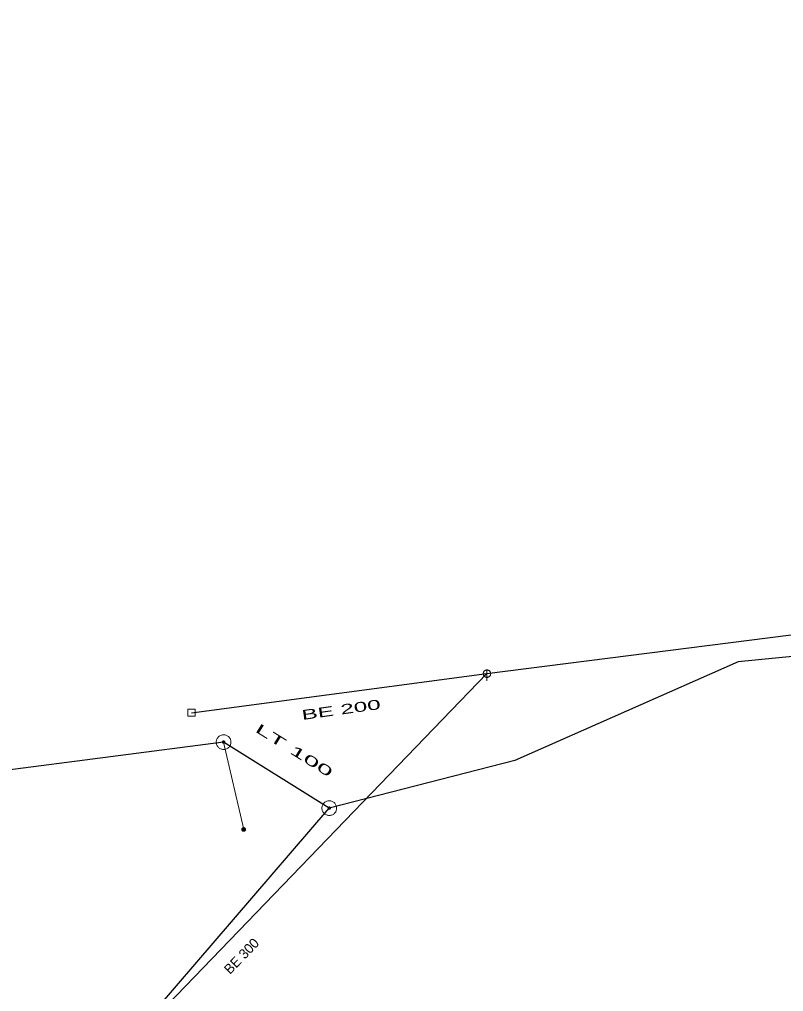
# Model space of a CAD drawing. Extents: x -687515 to -686506, y -974029 to -973461.
# Drawn here: x -687166.1 to -687114.2, y -973704.9 to -973638.9 of the extents above; entities that cross this region are included whole.
import ezdxf
from ezdxf.enums import TextEntityAlignment as Align

# ---------------------------------------------------------------- set-up
doc = ezdxf.new("R2010")
doc.units = 0
doc.header["$LTSCALE"] = 0.27
for name, color, linetype, lineweight in [('1', 7, 'Continuous', 13), ('14', 7, 'Continuous', 25), ('17', 7, 'Continuous', 25), ('22', 7, 'Continuous', 13), ('47', 7, 'Continuous', 13), ('9', 7, 'Continuous', 13)]:
    doc.layers.add(name, color=color, linetype=linetype, lineweight=lineweight)

msp = doc.modelspace()

# ---------------------------------------------------------------- linework, layer by layer
at = {"layer": '14'}
msp.add_line((-687167.553, -973717.772), (-687134.323, -973683.33), dxfattribs=at)
at = {"layer": '14', "lineweight": 13}
msp.add_line((-687152.206, -973687.982), (-687150.845, -973693.919), dxfattribs=at)
at = {"layer": '14'}
msp.add_lwpolyline([(-687154.392, -973685.982), (-687134.323, -973683.33), (-687071.261, -973675.291), (-687084.086, -973638.868)], dxfattribs=at)
at = {"layer": '17'}
for p, q in [((-687152.206, -973687.982), (-687218.589, -973696.579)), ((-687145.032, -973692.468), (-687152.206, -973687.982))]:
    msp.add_line(p, q, dxfattribs=at)
for points in [[(-687070.029, -973676.849), (-687070.692, -973676.951), (-687096.75, -973680.521), (-687117.267, -973682.535), (-687132.432, -973689.241), (-687145.032, -973692.468)], [(-687209.456, -973759.651), (-687158.031, -973707.595), (-687145.032, -973692.468)]]:
    msp.add_lwpolyline(points, dxfattribs=at)
at = {"layer": '22'}
msp.add_line((-687134.322, -973683.078), (-687134.323, -973683.821), dxfattribs=at)
for points in [[(-687134.071, -973683.33), (-687134.072, -973683.304), (-687134.076, -973683.278), (-687134.082, -973683.252), (-687134.092, -973683.228), (-687134.104, -973683.204), (-687134.118, -973683.182), (-687134.135, -973683.161), (-687134.153, -973683.143), (-687134.174, -973683.126), (-687134.196, -973683.112), (-687134.22, -973683.1), (-687134.244, -973683.09), (-687134.27, -973683.084), (-687134.296, -973683.08), (-687134.322, -973683.078), (-687134.348, -973683.079), (-687134.374, -973683.083), (-687134.4, -973683.089), (-687134.425, -973683.099), (-687134.448, -973683.111), (-687134.47, -973683.125), (-687134.491, -973683.142), (-687134.509, -973683.16), (-687134.526, -973683.181), (-687134.54, -973683.203), (-687134.552, -973683.227), (-687134.562, -973683.251), (-687134.569, -973683.277), (-687134.573, -973683.303), (-687134.575, -973683.329), (-687134.574, -973683.355), (-687134.57, -973683.381), (-687134.563, -973683.407), (-687134.553, -973683.432), (-687134.541, -973683.455), (-687134.527, -973683.477), (-687134.51, -973683.498), (-687134.492, -973683.516), (-687134.471, -973683.533), (-687134.449, -973683.547), (-687134.426, -973683.559), (-687134.401, -973683.569), (-687134.375, -973683.576), (-687134.349, -973683.58), (-687134.323, -973683.581), (-687134.297, -973683.581), (-687134.271, -973683.577), (-687134.245, -973683.57), (-687134.221, -973683.56), (-687134.197, -973683.548), (-687134.175, -973683.534), (-687134.154, -973683.517), (-687134.136, -973683.499), (-687134.119, -973683.478), (-687134.105, -973683.456), (-687134.093, -973683.433), (-687134.083, -973683.408), (-687134.077, -973683.382), (-687134.073, -973683.356)], [(-687154.64, -973685.733), (-687154.144, -973685.733), (-687154.144, -973686.23), (-687154.64, -973686.23)]]:
    msp.add_lwpolyline(points, close=True, dxfattribs=at)
at = {"layer": '47'}
for points in [[(-687151.708, -973687.93), (-687151.717, -973687.878), (-687151.73, -973687.828), (-687151.749, -973687.779), (-687151.772, -973687.732), (-687151.801, -973687.688), (-687151.834, -973687.647), (-687151.871, -973687.611), (-687151.912, -973687.578), (-687151.955, -973687.549), (-687152.002, -973687.525), (-687152.051, -973687.506), (-687152.101, -973687.493), (-687152.153, -973687.484), (-687152.205, -973687.482), (-687152.257, -973687.484), (-687152.309, -973687.493), (-687152.359, -973687.506), (-687152.409, -973687.525), (-687152.455, -973687.548), (-687152.499, -973687.577), (-687152.54, -973687.61), (-687152.577, -973687.647), (-687152.61, -973687.688), (-687152.639, -973687.731), (-687152.662, -973687.778), (-687152.681, -973687.827), (-687152.695, -973687.877), (-687152.703, -973687.929), (-687152.705, -973687.981), (-687152.703, -973688.033), (-687152.694, -973688.085), (-687152.681, -973688.135), (-687152.663, -973688.185), (-687152.639, -973688.231), (-687152.61, -973688.275), (-687152.578, -973688.316), (-687152.541, -973688.353), (-687152.5, -973688.386), (-687152.456, -973688.415), (-687152.409, -973688.438), (-687152.36, -973688.457), (-687152.311, -973688.471), (-687152.258, -973688.479), (-687152.206, -973688.481), (-687152.154, -973688.479), (-687152.102, -973688.47), (-687152.052, -973688.457), (-687152.003, -973688.439), (-687151.956, -973688.415), (-687151.912, -973688.386), (-687151.871, -973688.354), (-687151.835, -973688.317), (-687151.802, -973688.276), (-687151.773, -973688.232), (-687151.749, -973688.185), (-687151.73, -973688.136), (-687151.717, -973688.087), (-687151.708, -973688.034), (-687151.706, -973687.982)], [(-687152.124, -973687.973), (-687152.125, -973687.964), (-687152.128, -973687.956), (-687152.13, -973687.949), (-687152.134, -973687.941), (-687152.139, -973687.933), (-687152.145, -973687.927), (-687152.151, -973687.92), (-687152.157, -973687.915), (-687152.165, -973687.911), (-687152.172, -973687.907), (-687152.18, -973687.903), (-687152.189, -973687.901), (-687152.197, -973687.9), (-687152.205, -973687.899), (-687152.214, -973687.9), (-687152.223, -973687.901), (-687152.231, -973687.904), (-687152.238, -973687.906), (-687152.246, -973687.91), (-687152.254, -973687.915), (-687152.26, -973687.921), (-687152.267, -973687.927), (-687152.272, -973687.933), (-687152.277, -973687.941), (-687152.28, -973687.948), (-687152.284, -973687.956), (-687152.286, -973687.965), (-687152.287, -973687.973), (-687152.288, -973687.981), (-687152.287, -973687.99), (-687152.286, -973687.999), (-687152.283, -973688.007), (-687152.281, -973688.014), (-687152.277, -973688.022), (-687152.272, -973688.03), (-687152.267, -973688.036), (-687152.26, -973688.043), (-687152.254, -973688.048), (-687152.246, -973688.053), (-687152.239, -973688.056), (-687152.231, -973688.06), (-687152.222, -973688.062), (-687152.214, -973688.063), (-687152.206, -973688.064), (-687152.197, -973688.063), (-687152.188, -973688.062), (-687152.18, -973688.059), (-687152.173, -973688.057), (-687152.165, -973688.053), (-687152.157, -973688.048), (-687152.151, -973688.043), (-687152.144, -973688.036), (-687152.139, -973688.03), (-687152.135, -973688.022), (-687152.131, -973688.015), (-687152.127, -973688.007), (-687152.125, -973687.998), (-687152.124, -973687.99), (-687152.123, -973687.982)], [(-687144.532, -973692.462), (-687144.535, -973692.41), (-687144.544, -973692.358), (-687144.558, -973692.309), (-687144.577, -973692.26), (-687144.601, -973692.213), (-687144.631, -973692.169), (-687144.664, -973692.13), (-687144.701, -973692.093), (-687144.742, -973692.06), (-687144.786, -973692.032), (-687144.833, -973692.008), (-687144.882, -973691.991), (-687144.933, -973691.977), (-687144.985, -973691.97), (-687145.037, -973691.968), (-687145.089, -973691.971), (-687145.141, -973691.98), (-687145.191, -973691.994), (-687145.239, -973692.013), (-687145.286, -973692.037), (-687145.33, -973692.067), (-687145.37, -973692.1), (-687145.407, -973692.137), (-687145.44, -973692.178), (-687145.467, -973692.222), (-687145.491, -973692.269), (-687145.509, -973692.318), (-687145.522, -973692.369), (-687145.529, -973692.421), (-687145.531, -973692.473), (-687145.528, -973692.525), (-687145.519, -973692.577), (-687145.506, -973692.627), (-687145.486, -973692.675), (-687145.462, -973692.722), (-687145.433, -973692.766), (-687145.4, -973692.806), (-687145.363, -973692.843), (-687145.321, -973692.876), (-687145.277, -973692.903), (-687145.23, -973692.927), (-687145.182, -973692.945), (-687145.13, -973692.958), (-687145.078, -973692.965), (-687145.026, -973692.967), (-687144.974, -973692.964), (-687144.922, -973692.955), (-687144.873, -973692.942), (-687144.824, -973692.922), (-687144.777, -973692.898), (-687144.733, -973692.869), (-687144.694, -973692.836), (-687144.657, -973692.799), (-687144.624, -973692.757), (-687144.596, -973692.713), (-687144.572, -973692.666), (-687144.555, -973692.618), (-687144.541, -973692.566), (-687144.534, -973692.514)], [(-687144.95, -973692.467), (-687144.95, -973692.458), (-687144.952, -973692.45), (-687144.954, -973692.442), (-687144.957, -973692.434), (-687144.961, -973692.426), (-687144.966, -973692.419), (-687144.971, -973692.412), (-687144.977, -973692.406), (-687144.984, -973692.401), (-687144.991, -973692.396), (-687144.999, -973692.392), (-687145.007, -973692.389), (-687145.015, -973692.387), (-687145.023, -973692.385), (-687145.032, -973692.386), (-687145.041, -973692.386), (-687145.049, -973692.388), (-687145.057, -973692.39), (-687145.065, -973692.393), (-687145.073, -973692.397), (-687145.08, -973692.402), (-687145.087, -973692.407), (-687145.093, -973692.413), (-687145.099, -973692.42), (-687145.103, -973692.427), (-687145.107, -973692.435), (-687145.11, -973692.443), (-687145.112, -973692.451), (-687145.114, -973692.459), (-687145.113, -973692.468), (-687145.113, -973692.477), (-687145.111, -973692.485), (-687145.109, -973692.493), (-687145.106, -973692.501), (-687145.102, -973692.509), (-687145.098, -973692.516), (-687145.092, -973692.523), (-687145.086, -973692.529), (-687145.079, -973692.535), (-687145.072, -973692.539), (-687145.064, -973692.543), (-687145.056, -973692.546), (-687145.048, -973692.548), (-687145.04, -973692.55), (-687145.031, -973692.549), (-687145.022, -973692.549), (-687145.014, -973692.547), (-687145.006, -973692.545), (-687144.998, -973692.542), (-687144.99, -973692.538), (-687144.983, -973692.534), (-687144.976, -973692.528), (-687144.97, -973692.522), (-687144.965, -973692.515), (-687144.96, -973692.508), (-687144.956, -973692.5), (-687144.953, -973692.492), (-687144.951, -973692.484), (-687144.949, -973692.476)]]:
    msp.add_lwpolyline(points, close=True, dxfattribs=at)
at = {"layer": '9'}
for points in [[(-687150.718, -973693.919), (-687150.72, -973693.906), (-687150.722, -973693.893), (-687150.725, -973693.88), (-687150.73, -973693.868), (-687150.735, -973693.856), (-687150.743, -973693.845), (-687150.75, -973693.835), (-687150.761, -973693.825), (-687150.771, -973693.817), (-687150.782, -973693.809), (-687150.794, -973693.804), (-687150.806, -973693.799), (-687150.819, -973693.796), (-687150.831, -973693.794), (-687150.845, -973693.793), (-687150.858, -973693.794), (-687150.87, -973693.796), (-687150.884, -973693.799), (-687150.896, -973693.804), (-687150.907, -973693.809), (-687150.919, -973693.817), (-687150.929, -973693.825), (-687150.939, -973693.835), (-687150.946, -973693.845), (-687150.954, -973693.856), (-687150.96, -973693.868), (-687150.965, -973693.88), (-687150.968, -973693.893), (-687150.97, -973693.906), (-687150.971, -973693.919), (-687150.97, -973693.932), (-687150.968, -973693.945), (-687150.965, -973693.958), (-687150.96, -973693.97), (-687150.954, -973693.982), (-687150.946, -973693.993), (-687150.939, -973694.003), (-687150.929, -973694.013), (-687150.919, -973694.021), (-687150.907, -973694.028), (-687150.896, -973694.034), (-687150.884, -973694.039), (-687150.87, -973694.042), (-687150.858, -973694.044), (-687150.845, -973694.045), (-687150.831, -973694.044), (-687150.819, -973694.042), (-687150.806, -973694.039), (-687150.794, -973694.034), (-687150.782, -973694.028), (-687150.771, -973694.021), (-687150.761, -973694.013), (-687150.75, -973694.003), (-687150.743, -973693.993), (-687150.735, -973693.982), (-687150.73, -973693.97), (-687150.725, -973693.958), (-687150.722, -973693.945), (-687150.72, -973693.932)], [(-687150.739, -973693.919), (-687150.739, -973693.907), (-687150.74, -973693.897), (-687150.744, -973693.886), (-687150.748, -973693.876), (-687150.753, -973693.866), (-687150.759, -973693.857), (-687150.766, -973693.848), (-687150.774, -973693.84), (-687150.782, -973693.833), (-687150.792, -973693.827), (-687150.802, -973693.822), (-687150.811, -973693.818), (-687150.823, -973693.815), (-687150.833, -973693.813), (-687150.845, -973693.813), (-687150.856, -973693.813), (-687150.867, -973693.815), (-687150.878, -973693.818), (-687150.887, -973693.822), (-687150.897, -973693.827), (-687150.907, -973693.833), (-687150.916, -973693.84), (-687150.924, -973693.848), (-687150.931, -973693.857), (-687150.936, -973693.866), (-687150.941, -973693.876), (-687150.946, -973693.886), (-687150.949, -973693.897), (-687150.951, -973693.907), (-687150.951, -973693.919), (-687150.951, -973693.93), (-687150.949, -973693.941), (-687150.946, -973693.952), (-687150.941, -973693.962), (-687150.936, -973693.972), (-687150.931, -973693.981), (-687150.924, -973693.99), (-687150.916, -973693.998), (-687150.907, -973694.005), (-687150.897, -973694.011), (-687150.887, -973694.016), (-687150.878, -973694.02), (-687150.867, -973694.023), (-687150.856, -973694.025), (-687150.845, -973694.025), (-687150.833, -973694.025), (-687150.823, -973694.023), (-687150.811, -973694.02), (-687150.802, -973694.016), (-687150.792, -973694.011), (-687150.782, -973694.005), (-687150.774, -973693.998), (-687150.766, -973693.99), (-687150.759, -973693.981), (-687150.753, -973693.972), (-687150.748, -973693.962), (-687150.744, -973693.952), (-687150.74, -973693.941), (-687150.739, -973693.93)], [(-687150.757, -973693.919), (-687150.759, -973693.91), (-687150.76, -973693.901), (-687150.762, -973693.892), (-687150.766, -973693.884), (-687150.77, -973693.876), (-687150.775, -973693.868), (-687150.781, -973693.861), (-687150.787, -973693.855), (-687150.794, -973693.849), (-687150.802, -973693.844), (-687150.809, -973693.84), (-687150.818, -973693.837), (-687150.826, -973693.834), (-687150.836, -973693.833), (-687150.845, -973693.831), (-687150.853, -973693.833), (-687150.863, -973693.834), (-687150.872, -973693.837), (-687150.88, -973693.84), (-687150.887, -973693.844), (-687150.896, -973693.849), (-687150.902, -973693.855), (-687150.909, -973693.861), (-687150.914, -973693.868), (-687150.919, -973693.876), (-687150.924, -973693.884), (-687150.927, -973693.892), (-687150.929, -973693.901), (-687150.931, -973693.91), (-687150.932, -973693.919), (-687150.931, -973693.928), (-687150.929, -973693.937), (-687150.927, -973693.946), (-687150.924, -973693.954), (-687150.919, -973693.962), (-687150.914, -973693.97), (-687150.909, -973693.977), (-687150.902, -973693.983), (-687150.896, -973693.989), (-687150.887, -973693.994), (-687150.88, -973693.998), (-687150.872, -973694.001), (-687150.863, -973694.004), (-687150.853, -973694.005), (-687150.845, -973694.006), (-687150.836, -973694.005), (-687150.826, -973694.004), (-687150.818, -973694.001), (-687150.809, -973693.998), (-687150.802, -973693.994), (-687150.794, -973693.989), (-687150.787, -973693.983), (-687150.781, -973693.977), (-687150.775, -973693.97), (-687150.77, -973693.962), (-687150.766, -973693.954), (-687150.762, -973693.946), (-687150.76, -973693.937), (-687150.759, -973693.928)], [(-687150.777, -973693.919), (-687150.777, -973693.912), (-687150.78, -973693.905), (-687150.781, -973693.898), (-687150.784, -973693.892), (-687150.787, -973693.886), (-687150.791, -973693.88), (-687150.794, -973693.874), (-687150.799, -973693.869), (-687150.806, -973693.865), (-687150.811, -973693.861), (-687150.818, -973693.858), (-687150.824, -973693.855), (-687150.831, -973693.854), (-687150.838, -973693.852), (-687150.845, -973693.852), (-687150.852, -973693.852), (-687150.858, -973693.854), (-687150.865, -973693.855), (-687150.872, -973693.858), (-687150.879, -973693.861), (-687150.884, -973693.865), (-687150.89, -973693.869), (-687150.895, -973693.874), (-687150.899, -973693.88), (-687150.902, -973693.886), (-687150.906, -973693.892), (-687150.909, -973693.898), (-687150.911, -973693.905), (-687150.912, -973693.912), (-687150.912, -973693.919), (-687150.912, -973693.926), (-687150.911, -973693.933), (-687150.909, -973693.94), (-687150.906, -973693.946), (-687150.902, -973693.953), (-687150.899, -973693.958), (-687150.895, -973693.964), (-687150.89, -973693.969), (-687150.884, -973693.973), (-687150.879, -973693.977), (-687150.872, -973693.98), (-687150.865, -973693.983), (-687150.858, -973693.985), (-687150.852, -973693.986), (-687150.845, -973693.986), (-687150.838, -973693.986), (-687150.831, -973693.985), (-687150.824, -973693.983), (-687150.818, -973693.98), (-687150.811, -973693.977), (-687150.806, -973693.973), (-687150.799, -973693.969), (-687150.794, -973693.964), (-687150.791, -973693.958), (-687150.787, -973693.953), (-687150.784, -973693.946), (-687150.781, -973693.94), (-687150.78, -973693.933), (-687150.777, -973693.926)], [(-687150.798, -973693.919), (-687150.798, -973693.914), (-687150.799, -973693.909), (-687150.799, -973693.904), (-687150.802, -973693.9), (-687150.804, -973693.895), (-687150.807, -973693.891), (-687150.809, -973693.888), (-687150.814, -973693.884), (-687150.816, -973693.881), (-687150.821, -973693.878), (-687150.826, -973693.876), (-687150.83, -973693.874), (-687150.835, -973693.873), (-687150.84, -973693.872), (-687150.845, -973693.872), (-687150.85, -973693.872), (-687150.855, -973693.873), (-687150.86, -973693.874), (-687150.864, -973693.876), (-687150.869, -973693.878), (-687150.873, -973693.881), (-687150.877, -973693.884), (-687150.88, -973693.888), (-687150.882, -973693.891), (-687150.886, -973693.895), (-687150.887, -973693.9), (-687150.89, -973693.904), (-687150.891, -973693.909), (-687150.892, -973693.914), (-687150.892, -973693.919), (-687150.892, -973693.924), (-687150.891, -973693.929), (-687150.89, -973693.934), (-687150.887, -973693.938), (-687150.886, -973693.943), (-687150.882, -973693.947), (-687150.88, -973693.951), (-687150.877, -973693.954), (-687150.873, -973693.956), (-687150.869, -973693.96), (-687150.864, -973693.962), (-687150.86, -973693.964), (-687150.855, -973693.965), (-687150.85, -973693.966), (-687150.845, -973693.966), (-687150.84, -973693.966), (-687150.835, -973693.965), (-687150.83, -973693.964), (-687150.826, -973693.962), (-687150.821, -973693.96), (-687150.816, -973693.956), (-687150.814, -973693.954), (-687150.809, -973693.951), (-687150.807, -973693.947), (-687150.804, -973693.943), (-687150.802, -973693.938), (-687150.799, -973693.934), (-687150.799, -973693.929), (-687150.798, -973693.924)], [(-687150.818, -973693.919), (-687150.818, -973693.916), (-687150.818, -973693.913), (-687150.819, -973693.911), (-687150.82, -973693.907), (-687150.821, -973693.905), (-687150.823, -973693.903), (-687150.825, -973693.901), (-687150.826, -973693.899), (-687150.829, -973693.897), (-687150.831, -973693.895), (-687150.833, -973693.894), (-687150.837, -973693.893), (-687150.838, -973693.892), (-687150.842, -973693.892), (-687150.845, -973693.892), (-687150.848, -973693.892), (-687150.851, -973693.892), (-687150.853, -973693.893), (-687150.856, -973693.894), (-687150.858, -973693.895), (-687150.86, -973693.897), (-687150.864, -973693.899), (-687150.865, -973693.901), (-687150.867, -973693.903), (-687150.869, -973693.905), (-687150.87, -973693.907), (-687150.87, -973693.911), (-687150.872, -973693.913), (-687150.872, -973693.916), (-687150.873, -973693.919), (-687150.872, -973693.922), (-687150.872, -973693.925), (-687150.87, -973693.928), (-687150.87, -973693.93), (-687150.869, -973693.933), (-687150.867, -973693.934), (-687150.865, -973693.938), (-687150.864, -973693.94), (-687150.86, -973693.941), (-687150.858, -973693.943), (-687150.856, -973693.944), (-687150.853, -973693.945), (-687150.851, -973693.946), (-687150.848, -973693.946), (-687150.845, -973693.947), (-687150.842, -973693.946), (-687150.838, -973693.946), (-687150.837, -973693.945), (-687150.833, -973693.944), (-687150.831, -973693.943), (-687150.829, -973693.941), (-687150.826, -973693.94), (-687150.825, -973693.938), (-687150.823, -973693.934), (-687150.821, -973693.933), (-687150.82, -973693.93), (-687150.819, -973693.928), (-687150.818, -973693.925), (-687150.818, -973693.922)], [(-687150.837, -973693.919), (-687150.837, -973693.918), (-687150.837, -973693.917), (-687150.838, -973693.917), (-687150.838, -973693.916), (-687150.838, -973693.915), (-687150.838, -973693.914), (-687150.838, -973693.914), (-687150.84, -973693.913), (-687150.84, -973693.913), (-687150.841, -973693.912), (-687150.842, -973693.912), (-687150.843, -973693.912), (-687150.843, -973693.911), (-687150.843, -973693.911), (-687150.845, -973693.911), (-687150.846, -973693.911), (-687150.847, -973693.911), (-687150.847, -973693.912), (-687150.848, -973693.912), (-687150.848, -973693.912), (-687150.85, -973693.913), (-687150.85, -973693.913), (-687150.851, -973693.914), (-687150.851, -973693.914), (-687150.852, -973693.915), (-687150.852, -973693.916), (-687150.853, -973693.917), (-687150.853, -973693.917), (-687150.853, -973693.918), (-687150.853, -973693.919), (-687150.853, -973693.92), (-687150.853, -973693.921), (-687150.853, -973693.921), (-687150.852, -973693.922), (-687150.852, -973693.923), (-687150.851, -973693.924), (-687150.851, -973693.924), (-687150.85, -973693.925), (-687150.85, -973693.925), (-687150.848, -973693.926), (-687150.848, -973693.926), (-687150.847, -973693.927), (-687150.847, -973693.927), (-687150.846, -973693.927), (-687150.845, -973693.927), (-687150.843, -973693.927), (-687150.843, -973693.927), (-687150.843, -973693.927), (-687150.842, -973693.926), (-687150.841, -973693.926), (-687150.84, -973693.925), (-687150.84, -973693.925), (-687150.838, -973693.924), (-687150.838, -973693.924), (-687150.838, -973693.923), (-687150.838, -973693.922), (-687150.838, -973693.921), (-687150.837, -973693.921), (-687150.837, -973693.92)]]:
    msp.add_lwpolyline(points, close=True, dxfattribs=at)

# ---------------------------------------------------------------- texts
at = {"layer": '1'}
for s, rotation, width, p in [('BE 200', 8, 1.85, (-687144.184, -973686.103)), ('LT 100', 328, 2.15, (-687147.59, -973688.82))]:
    msp.add_text(s, height=0.6667, rotation=rotation, dxfattribs=dict(at, width=width)).set_placement(p, align=Align.CENTER)
msp.add_text('BE 300', height=0.6667, rotation=46, dxfattribs=at).set_placement((-687150.755, -973702.755), align=Align.CENTER)

doc.saveas('drawing.dxf')
